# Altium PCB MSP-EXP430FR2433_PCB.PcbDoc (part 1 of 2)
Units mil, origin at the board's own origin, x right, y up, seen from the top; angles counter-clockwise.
Board outline 2300 x 2900 mil, 4 copper layers (Top Layer, VCC Layer, GND Layer, Bottom Layer), stack 30.634 mil thick; 130 components, 92 nets, 410 pads, 310 vias.
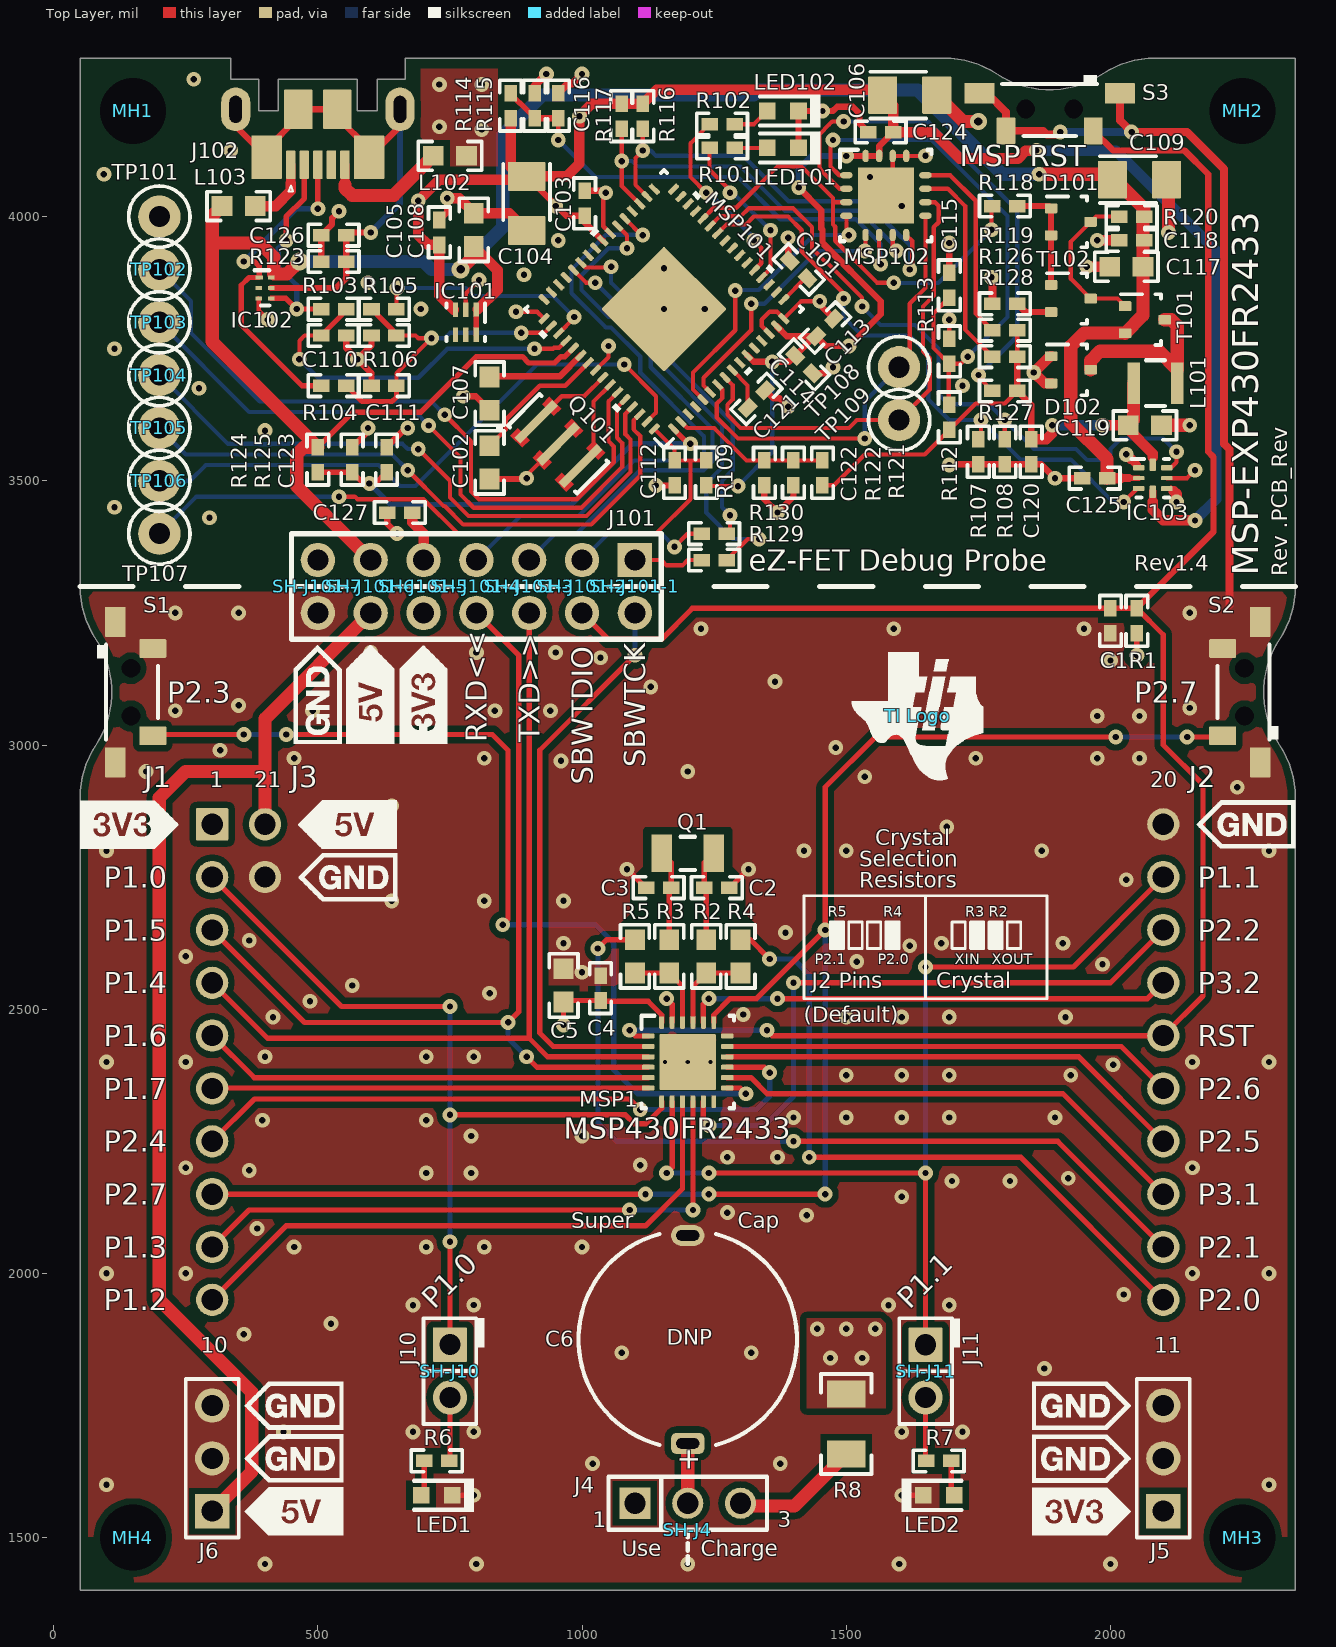
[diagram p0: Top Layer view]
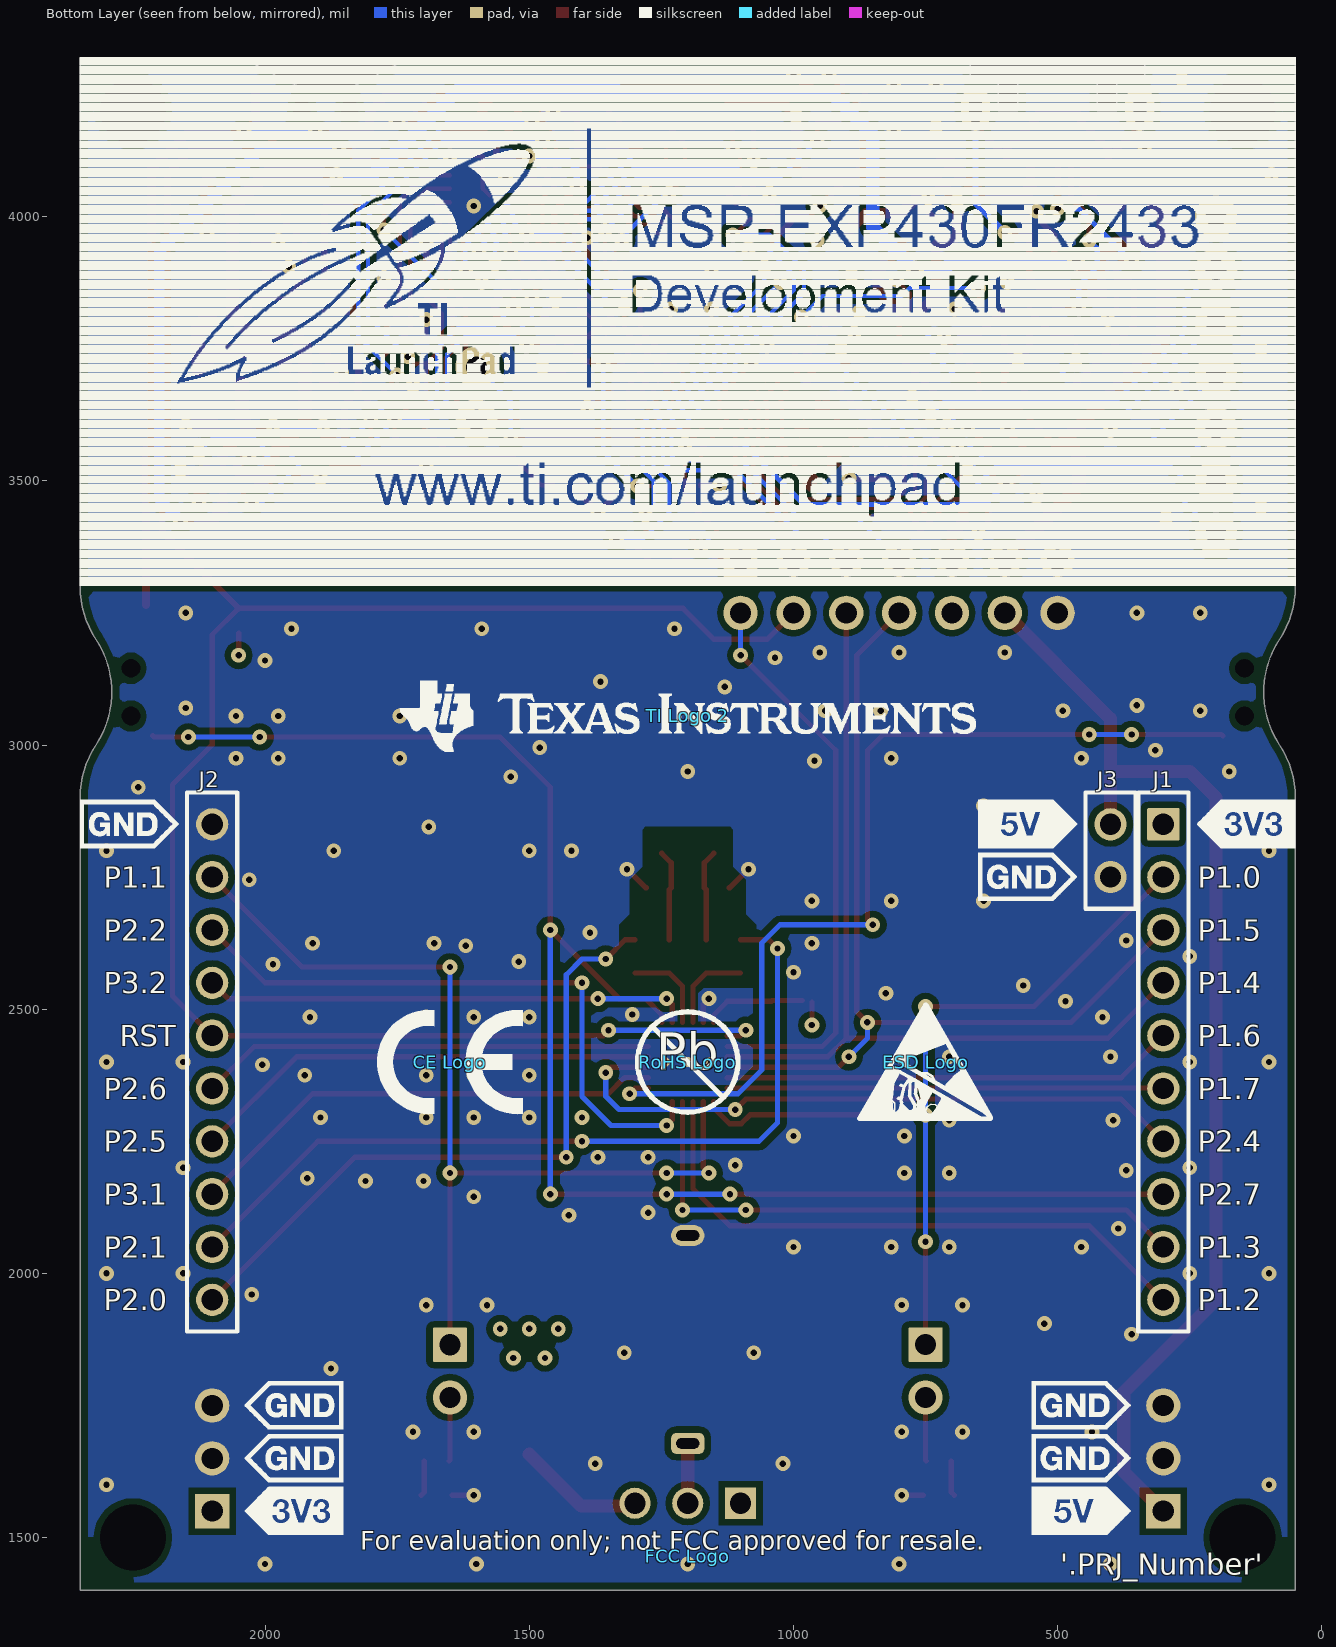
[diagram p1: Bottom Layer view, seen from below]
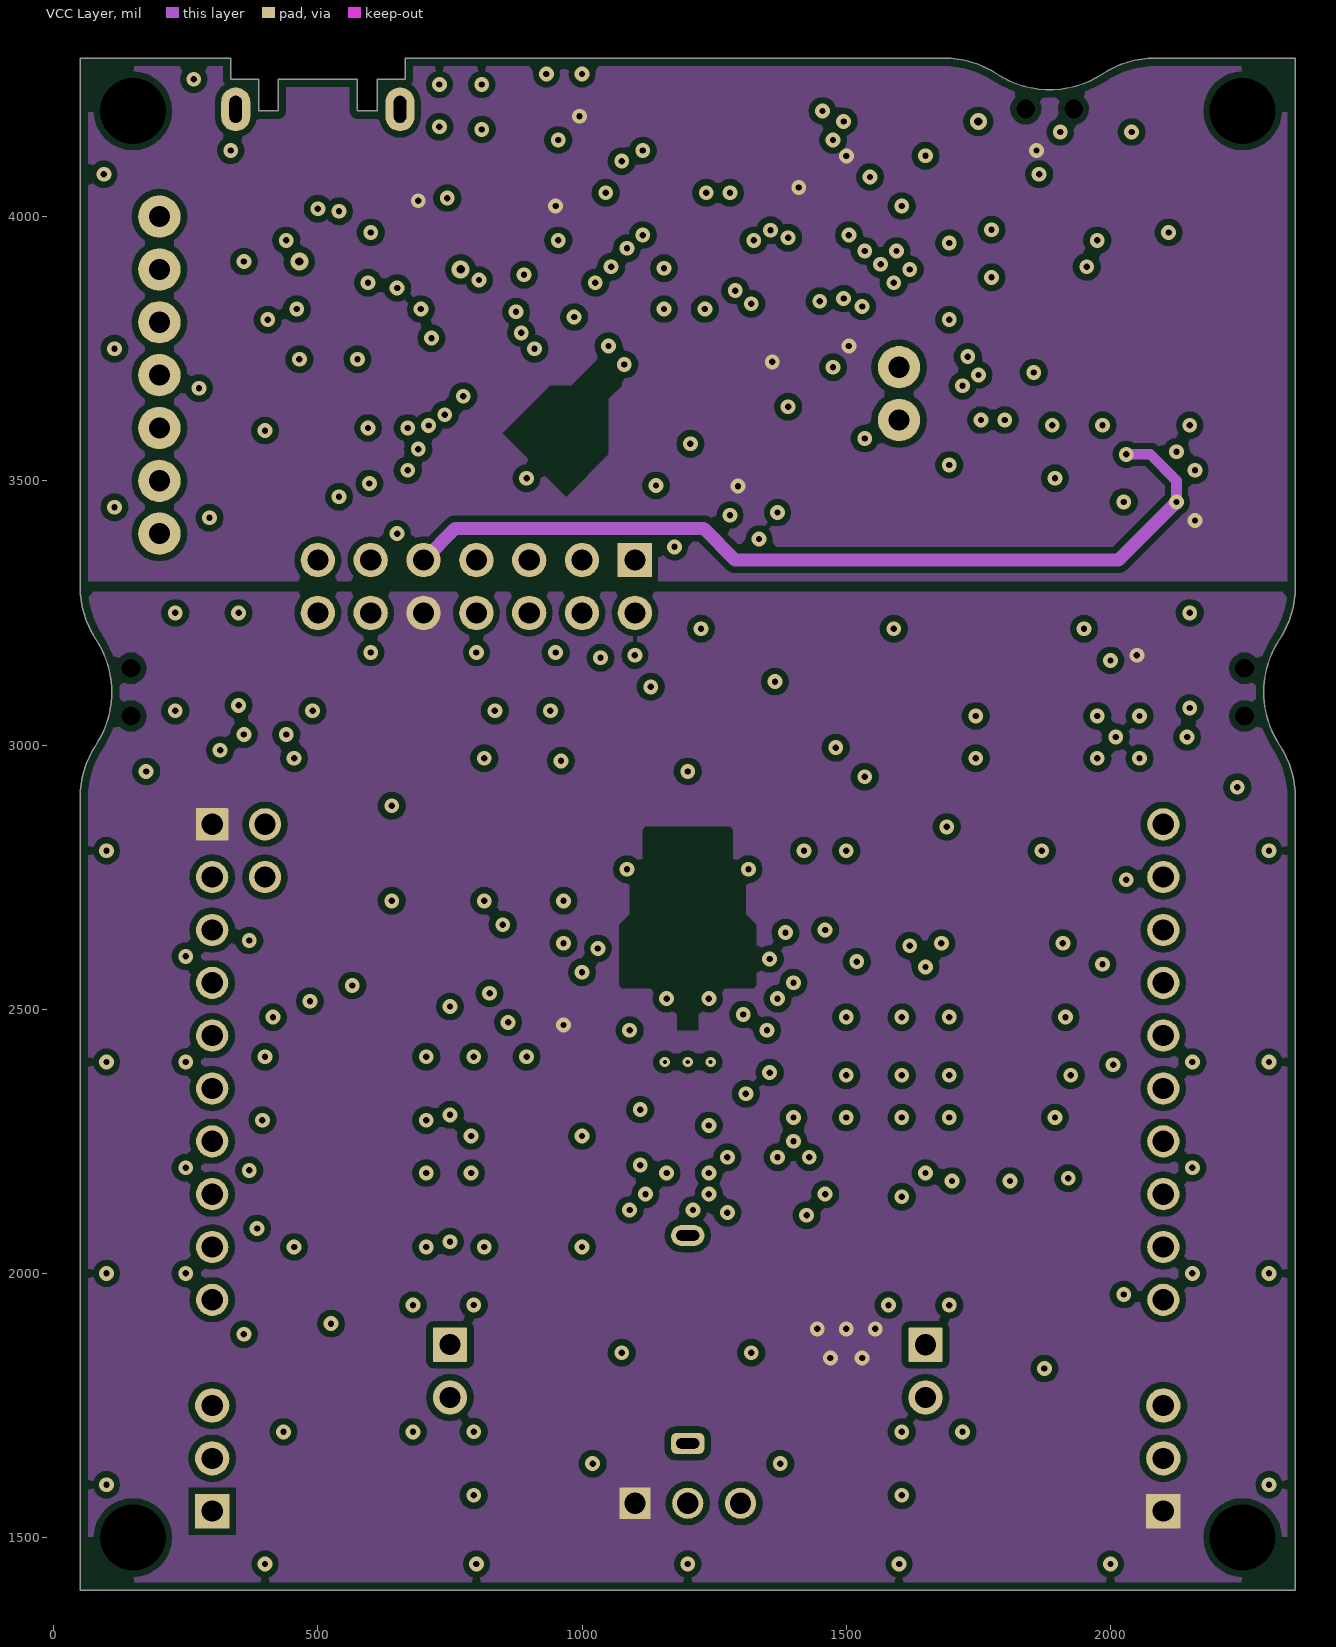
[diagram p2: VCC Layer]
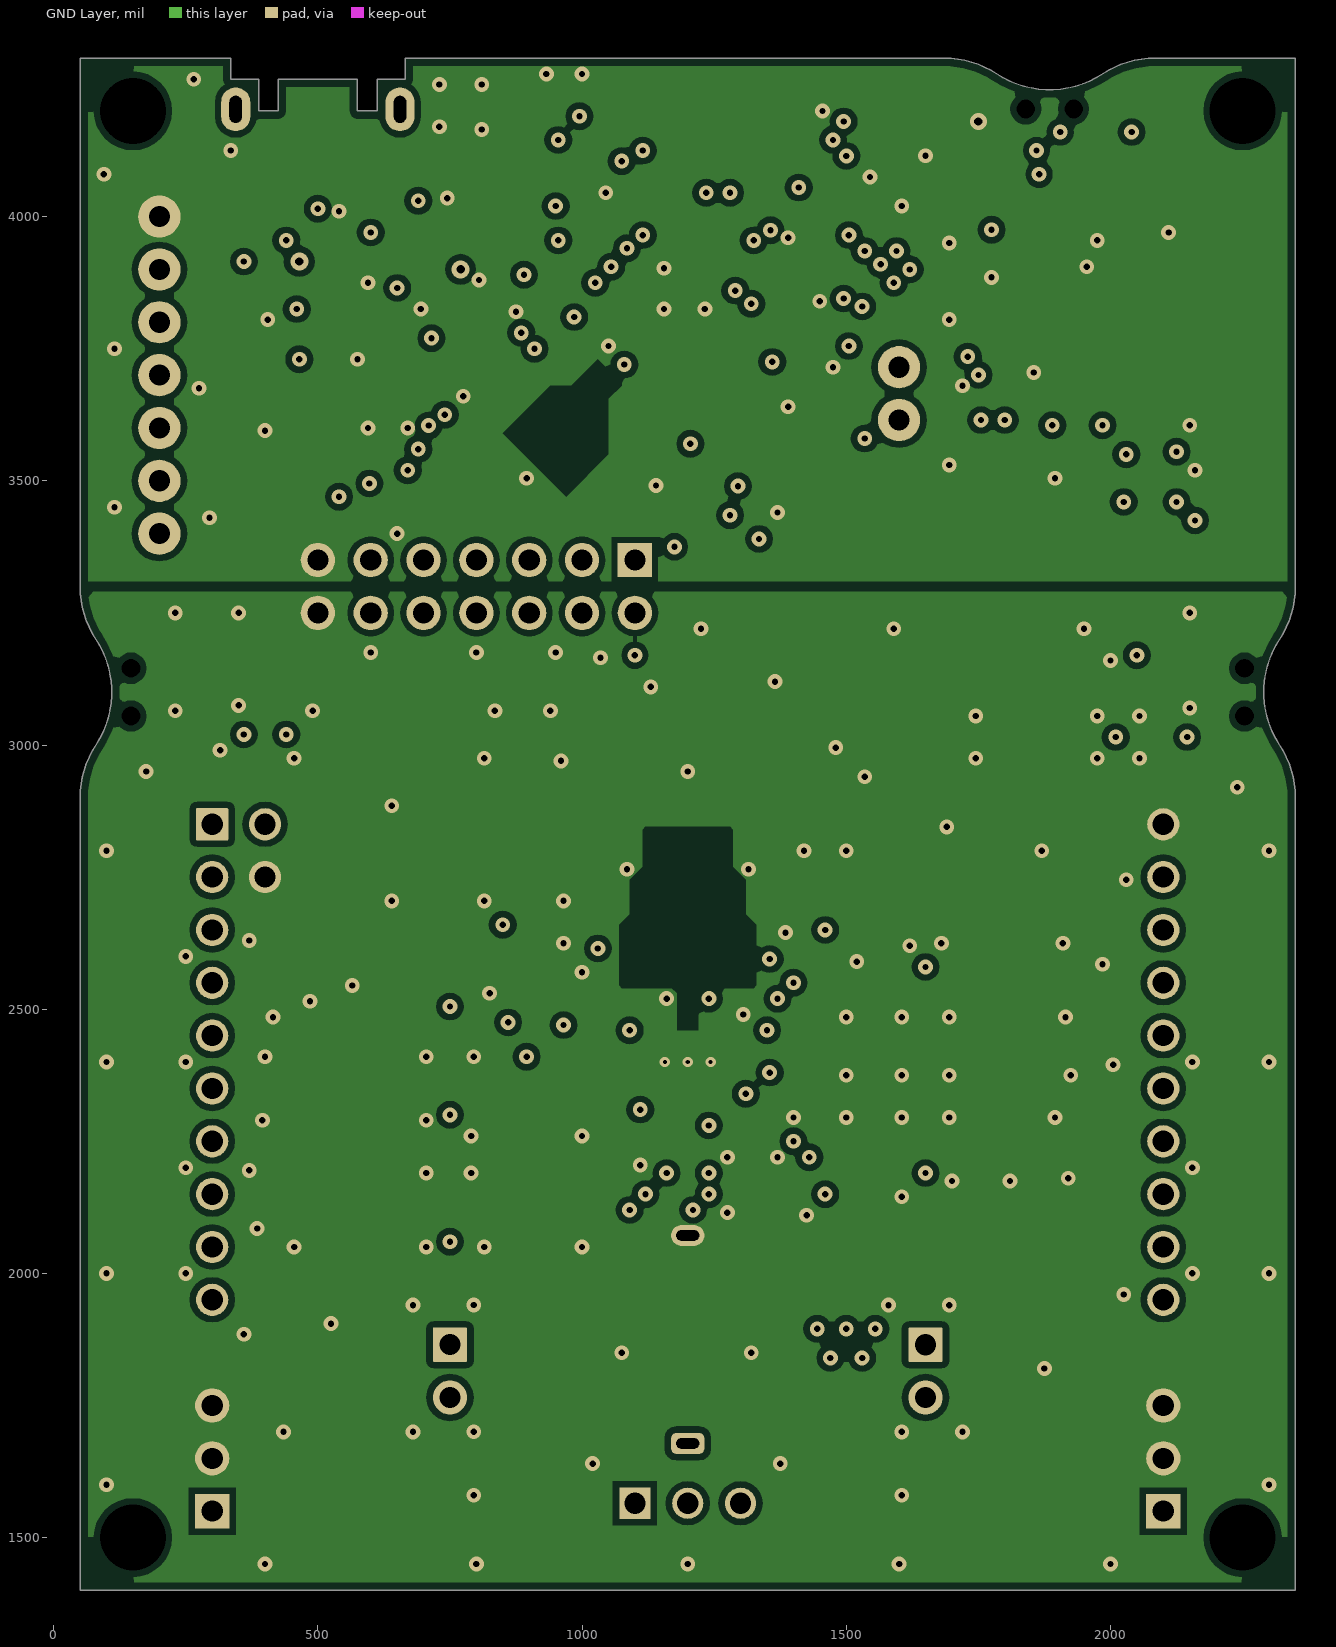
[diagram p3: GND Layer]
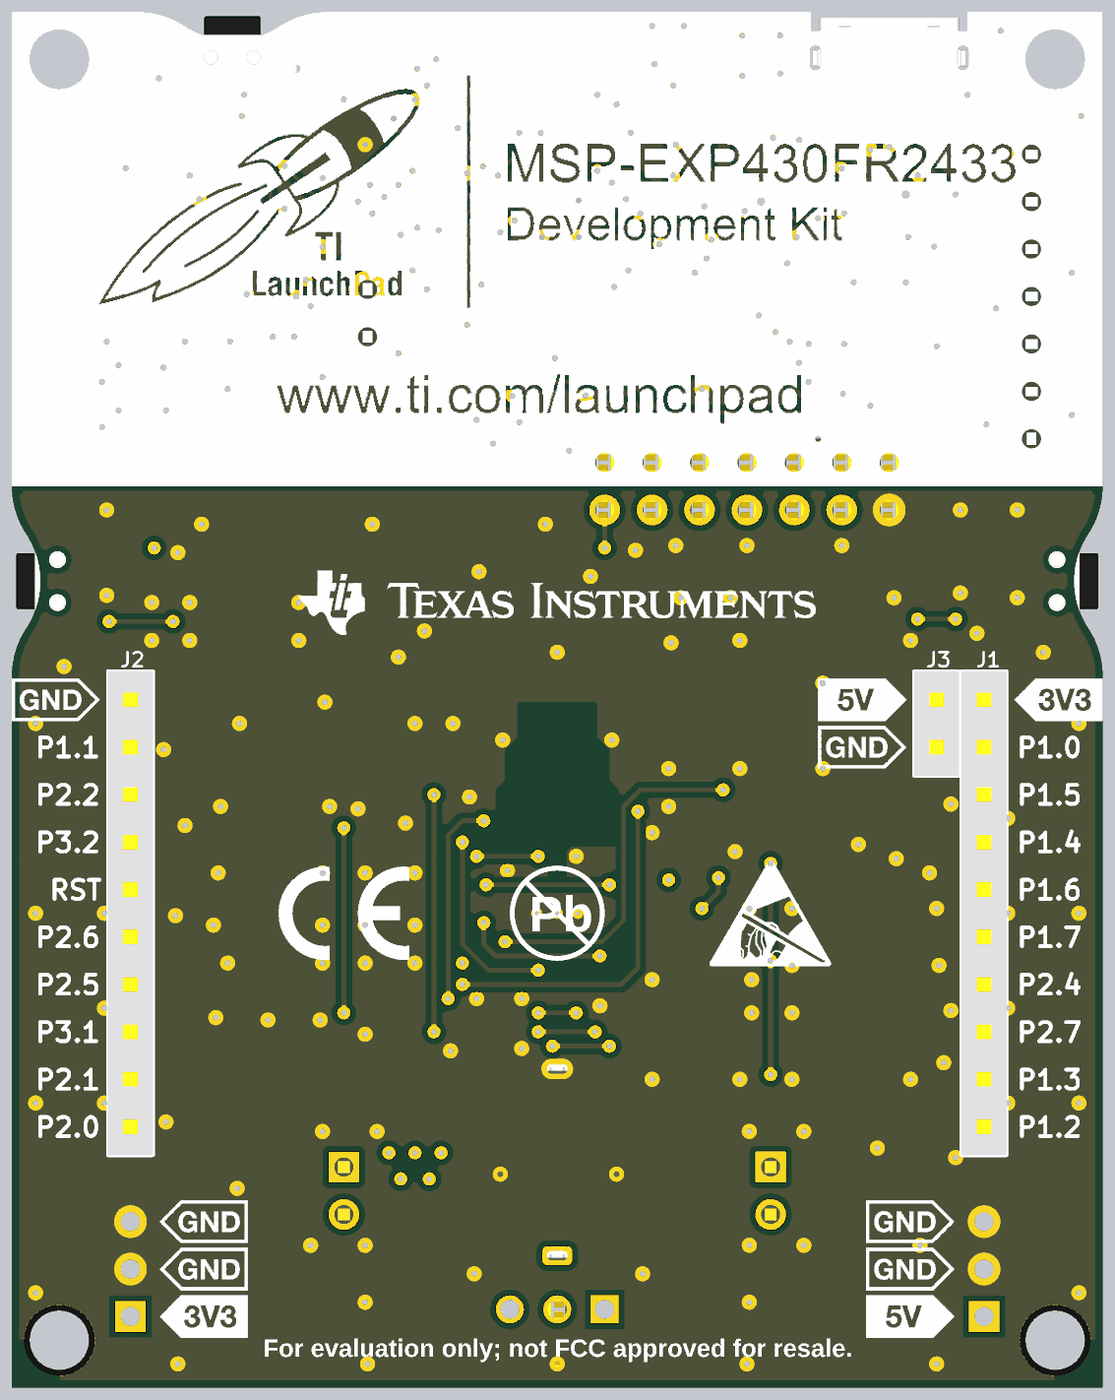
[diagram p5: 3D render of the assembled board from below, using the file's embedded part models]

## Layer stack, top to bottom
Top Solder: solder mask 0.4, Solder Resist, Dk 3.5
Top Layer: signal copper 1.4
Dielectric 2: core 10, Dk 4.2
VCC Layer: signal copper 1.417
Dielectric1: prepreg 5, FR-4, Dk 4.2
GND Layer: signal copper 1.417
Dielectric 3: core 10, Dk 4.2
Bottom Layer: signal copper 1.4
Bottom Solder: solder mask 0.4, Solder Resist, Dk 3.5

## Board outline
50,1400 50,2900 cw(c231.67,2900) 80,3000 ccw(c-71.67,3100) 80,3200 cw(c231.67,3300) 50,3300 50,4300 335,4300 335,4260 388,4260 388,4200 425,4200 425,4260 575,4260 575,4200 612,4200 612,4260 665,4260 665,4300 1685,4300 cw(c1685,4118.33) 1785,4270 ccw(c1885,4421.67) 1985,4270 cw(c2085,4118.33) 2085,4300 2350,4300 2350,3300 cw(c2168.33,3300) 2320,3200 ccw(c2471.67,3100) 2320,3000 cw(c2168.33,2900) 2350,2900 2350,1400

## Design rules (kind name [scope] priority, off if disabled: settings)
AcuteAngle [All] p1: minimum=4.50000000000000E+0001 checktracksonly=FALSE
AssemblyTestPointUsage [All] p1: valid=2
BoardOutlineClearance BoardOutlineClearance_MountingHoles [OnCopper and InComponentClass('Mounting Holes')] p1: gap=15
BoardOutlineClearance BoardOutlineClearance_Poly [OnCopper and IsPoly] p2: gap=15
BoardOutlineClearance [OnCopper and Not InComponentClass('Logo') and not InComponentClass('FiducialMark') and not InRegion(1000,500,4000,800) and not InPoly] p3: gap=10
Clearance Clearance_Keepouts [((IsTrack Or IsArc) And Not InPoly) And IsFree and IsKeepOut vs ((IsTrack Or IsArc) And Not InPoly) And IsFree and IsKeepOut] p1: gap=0
Clearance Clearance_Poly [InPolygon] p2: gap=12
Clearance [All] p3: gap=7.87
ComponentClearance ComponentClearance_MountingHoles_FiducialMarks [InComponentClass('Mounting Holes') vs InComponentClass('FiducialMark')] p1: gap=50 collisioncheckmode=3 verticalgap=10 showdistances=FALSE
ComponentClearance ComponentClearance_Shunt [InComponentClass('Header') vs InComponentClass('Shunt')] p2: gap=0 collisioncheckmode=3 verticalgap=0 showdistances=FALSE
ComponentClearance ComponentClearance_Logo [InComponentClass('Logo')] p3: gap=0 collisioncheckmode=3 verticalgap=10 showdistances=FALSE
ComponentClearance ComponentClearance_ScrewToNut [(HasFootprint('NY PMS 440 0025 PH')) vs (HasFootprint('Keystone_1902C'))] p4: gap=5 collisioncheckmode=3 verticalgap=10 showdistances=FALSE
ComponentClearance ComponentClearance_MountingHoles [InComponentClass('Mounting Holes')] p5: gap=0 collisioncheckmode=3 verticalgap=100000 showdistances=FALSE
ComponentClearance ComponentClearance_SmallPassives [HasFootprint('0201*') or HasFootprint('0402*') or HasFootprint('0508') or HasFootprint('0603*') or HasFootprint('0612') or HasFootprint('0805*') or HasFootprint('0815*') or HasFootprint('0830*') or HasFootprint('1206*') or HasFootprint('1210*') or HasFootprint('1808*') or HasFootprint('1812*') or HasFootprint('1825*') or HasFootprint('2010*') or HasFootprint('2220*') or HasFootprint('2225*') or HasFootprint('2512*') or HasFootprint('2728*') or HasFootprint('3518*') vs HasFootprint('0201*') or HasFootprint('0402*') or HasFootprint('0508') or HasFootprint('0603*') or HasFootprint('0612') or HasFootprint('0805*') or HasFootprint('0815*') or HasFootprint('0830*') or HasFootprint('1206*') or HasFootprint('1210*') or HasFootprint('1808*') or HasFootprint('1812*') or HasFootprint('1825*') or HasFootprint('2010*') or HasFootprint('2220*') or HasFootprint('2225*') or HasFootprint('2512*') or HasFootprint('2728*') or HasFootprint('3518*')] p6: gap=0 collisioncheckmode=3 verticalgap=0 showdistances=FALSE
ComponentClearance ComponentClearance_THtoSMT [IsThruComponent vs IsSMTComponent] p7: gap=0 collisioncheckmode=3 verticalgap=0 showdistances=FALSE
ComponentClearance ComponentClearance_THtoTH [IsThruComponent vs IsThruComponent] p8: gap=0 collisioncheckmode=3 verticalgap=0 showdistances=FALSE
ComponentClearance [All] p9: gap=0 collisioncheckmode=3 verticalgap=0 showdistances=FALSE
DiffPairsRouting [All] p1: maxlimit=100 minlimit=10 mostfreqgap=10 toplayer_minwidth=15 toplayer_maxwidth=15 toplayer_prefwidth=15 midlayer1_minwidth=15 midlayer1_maxwidth=15 midlayer1_prefwidth=15 midlayer2_minwidth=15 midlayer2_maxwidth=15 midlayer2_prefwidth=15 bottomlayer_minwidth=15 bottomlayer_maxwidth=15 bottomlayer_prefwidth=15 maxuncoupledlength=1000
FabricationTestPointUsage TestPointUsage [All] p1: valid=2 allowmultiple=FALSE
FabricationTestpoint Testpoint [All] p1: side=3 testpointundercomponent=TRUE minsize=40 maxsize=100 preferedsize=60 minholesize=0 maxholesize=40 preferedholesize=32 testpointgrid=1 allowsidetop=TRUE allowsidebottom=TRUE usegrid=TRUE gridtolerance=0.01
FanoutControl Fanout_LCC [IsLCC] p1: bgadir=Out bgaviamode=Centered fanoutstyle=Auto fanoutdirection=Alternating viagrid=1 // Fanout_LCC (Default Rule)
FanoutControl Fanout_BGA [IsBGA] p2: bgadir=Out bgaviamode=Centered fanoutstyle=Auto fanoutdirection=Alternating viagrid=1 // Fanout_BGA (Default Rule)
FanoutControl Fanout_Default [All] p4: bgadir=Out bgaviamode=Centered fanoutstyle=Auto fanoutdirection=Alternating viagrid=1 // Fanout_Default (Default Rule)
FanoutControl Fanout_Small [(CompPinCount < 5)] p5: bgadir=Out bgaviamode=Centered fanoutstyle=Auto fanoutdirection=OutThenIn viagrid=1 // Fanout_Small (Default Rule)
HoleSize [All] p1: absolutevalues=TRUE maxlimit=251 minlimit=7.87 maxpercent=80.000 minpercent=20.000
MinimumAnnularRing MinimumAnnularRing_ThermalPadVias [IsVia and InAnyComponent] p1: minimumring=5.91
MinimumAnnularRing [All] p2: minimumring=8
MinimumSolderMaskSliver MinimumSolderMaskSliver_Logo [InComponentClass('Logo') vs InComponentClass('Logo')] p1: minsoldermaskwidth=0.7
MinimumSolderMaskSliver [All] p2: minsoldermaskwidth=3.94
PlaneClearance [All] p1: clearance=10
PlaneConnect [All] p1: planeconnectstyle=Relief reliefexpansion=10 reliefentries=4 reliefconductorwidth=10 reliefairgap=10
PolygonConnect [All] p1: connectstyle=Direct reliefconductorwidth=10 reliefentries=4 polygonreliefangle="90 Angle" airgapwidth=10
RoutingVias ThermalPadVias [IsVia and InAnyComponent] p1: holewidth=7.87 width=19.68 viastyle="Through Hole" minholewidth=7.87 minwidth=19.68 maxholewidth=16 maxwidth=30
RoutingVias [All] p2: holewidth=12 width=28 viastyle="Through Hole" minholewidth=7.87 minwidth=26 maxholewidth=40 maxwidth=65
SilkToBoardRegionClearance [Not ((IsComment or IsDesignator) And (Hide <> 'False')) and not InRegion(1000,500,4000,800)] p1:
SilkToSilkClearance SilkToSilkClearance_Pb-FreeLogo [(HasFootprint('Pb-Free_Overlay_Medium') OR HasFootprint('Pb-Free_Overlay_Small')) vs (HasFootprint('Pb-Free_Overlay_Medium') OR HasFootprint('Pb-Free_Overlay_Small'))] p1: silktosilkclearance=0
SilkToSilkClearance [All] p2: silktosilkclearance=4
SilkToSolderMaskClearance SilkToComponentPadClearance [(IsPad or IsFill or IsRegion) and InAnycomponent] p1: minsilkscreentomaskgap=5 clearancetoexposedcopper=TRUE
SilkToSolderMaskClearance "Silk to Solder Mask Opening" [All] p2: minsilkscreentomaskgap=4 clearancetoexposedcopper=FALSE
SolderMaskExpansion SolderMaskExpansion_via [isvia] p1: expansion=-17
SolderMaskExpansion [All] p2: expansion=1.97
Width [All] p1: maxlimit=100 minlimit=6 preferedwidth=10 checkconnectedcopper=TRUE
14 further rules are at their usual default settings.

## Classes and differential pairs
component class Shunt: SH-J4 SH-J10 SH-J11 SH-J101-1 SH-J101-2 SH-J101-3 SH-J101-4 SH-J101-5 SH-J101-6 SH-J101-7
component class Logo: "TI Logo" "TI Logo 2"
component class LaunchPad_Hardware: "CE Logo" "ESD Logo" "FCC Logo" MH1 MH2 MH3 MH4 "RoHS Logo" "TI Logo" "TI Logo 2"
component class Header: J4 J5 J6 J10 J11 J101
component class LaunchPad_eZFET_1.4: C101 C102 C103 C104 C105 C106 C107 C108 C109 C110 C111 C112 C113 C114 C115 C116 C117 C118 C119 C120 C121 C122 C123 C124 C125 C126 C127 D101 D102 IC101 IC102 IC103 J101 J102 L101 L102 L103 LED101 LED102 MSP101 MSP102 Q101 R101 R102 R103 R104 R105 R106 R107 R108 R109 R112 R113 R114 R115 R116 R117 R118 R119 R120 R121 R122 R123 R124 R125 R126 R127 R128 R129 R130 SH-J101-1 SH-J101-2 SH-J101-3 SH-J101-4 SH-J101-5 SH-J101-6 SH-J101-7 T101 T102 TP101 TP102 TP103 TP104 TP105 TP106 TP107 TP108 TP109
component class LaunchPad_TargetDevice: C1 C2 C3 C4 C5 C6 J1 J2 J3 J4 J5 J6 J10 J11 LED1 LED2 MSP1 Q1 R1 R2 R3 R4 R5 R6 R7 R8 S1 S2 S3 SH-J4 SH-J10 SH-J11

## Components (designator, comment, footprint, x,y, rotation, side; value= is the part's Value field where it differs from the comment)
C1 "GRM155R71H102KA01D" 0402 2000,3235 r270 top
C2 "GRM1555C1E120JA01D" 0402 1255,2730 r0 top
C3 "GRM1555C1E120JA01D" 0402 1145,2730 r180 top
C4 "GRM155R61H104ME14D" 0402 1035,2540 r90 top
C5 "GRM188R60J106ME84" 0603 965,2545 r270 top
C6 "EEC-S0HD224H" SD_1050x600 1200,1875 r90 top
C101 "GRM155R61C474KE01" 0402 1410,3900 r315 top
C102 "GRM188R61C224KA88D" 0603 825,3535 r90 top
C103 "GRM155R61A104KA01D" 0402 1005,4025 r270 top
C104 "293D106X0010A2TE3" 3216-18 895,4025 r270 top
C105 "GRM155R61A104KA01D" 0402 730,3970 r270 top
C106 "293D475X9010A2TE3" 3216-18 1620,4230 r0 top
C107 "GRM188R61C224KA88D" 0603 825,3665 r90 top
C108 "GRM185R61A105KE36D" 0603 795,3975 r270 top
C109 "293D475X9010A2TE3" 3216-18 2055,4070 r0 top
C110 "GRM1555C1H100JA01D" 0402 530,3775 r0 top
C111 "GRM1555C1H100JA01D" 0402 625,3680 r180 top
C112 "GRM155R71H102KA01D" 0402 1175,3515 r90 top
C113 "GRM155R61A104KA01D" 0402 1460,3790 r225 top
C114 "GRM155R61A104KA01D" 0402 1420,3720 r135 top
C115 "GRM1555C1H330JA01D" 0402 1695,3870 r270 top
C116 "GRM1555C1H330JA01D" 0402 955,4210 r270 top
C117 "GRM188R61C475KAAJ" 0603 2030,3905 r0 top
C118 "GRM155R61A104KA01D" 0402 2040,3955 r0 top
C119 "GRM188R61C475KAAJ" 0603 2065,3605 r180 top
C120 "GRM155R61A104KA01D" 0402 1850,3555 r90 top
C121 "GRM155R61A104KA01D" 0402 1330,3655 r225 top
C122 "GRM1555C1H330JA01D" 0402 1345,3515 r90 top
C123 "GRM1555C1H330JA01D" 0402 630,3540 r270 top
C124 "GRM155R61A104KA01D" 0402 1565,4160 r0 top
C125 "GRM155R61A104KA01D" 0402 1970,3505 r0 top
C126 "GRM155R61A224KE19D" 0402 530,3965 r0 top
C127 "GRM1555C1H101JA01D" 0402 655,3440 r180 top
"CE Logo" "CE Mark" CE_Mark_5mm 1650,2400 r180 bottom
D101 "BAS40-05W,115" SOT-323 1925,3990 r0 top
D102 "BAS40-05W,115" SOT-323 1925,3710 r0 top
"ESD Logo" "ESD Susceptible" ESD_Overlay_Medium 750,2400 r180 bottom
"FCC Logo" "FCC disclaimer" FCC_disclaimer 1200,1465 r90 bottom
IC101 "TLV70033DSET" DSE0006A 780,3800 r270 top
IC102 "TPD4E004DRYR" DRY0006A 400,3865 r0 top
IC103 "TS5A21366RSER" RSE0008A 2080,3505 r0 top
J1 "SSQ-110-03-F-S" BoosterPack_20pin_J1 300,2400 r180 bottom
J2 "SSQ-110-03-F-S" BoosterPack_20pin_J2 2100,2400 r180 bottom
J3 "SSQ-102-03-F-S" BoosterPack_20pin_J3 400,2800 r180 bottom
J4 "PEC03SAAN" CONN_PEC03SAAN 1200,1565 r0 top
J5 "PEC03SAAN" PEC03SAAN_Launchpad_3V3 2100,1650 r90 top
J6 "PEC03SAAN" PEC03SAAN_Launchpad_5V0 300,1650 r90 top
J10 "TSW-102-07-G-S" TSW-102-07-G-S 750,1815.14 r270 top
J11 "TSW-102-07-G-S" TSW-102-07-G-S 1650,1815 r270 top
J101 "PEC07DAAN" PEC07DAAN_Launchpad_EZ-FET 800,3300 r180 top
J102 "1051640001" Molex_1051640001 500,4260 r180 top
L101 "CBC2518T2R2M" CBC2518 2085,3685 r180 top
L102 "742792622" 0603 750,4115 r0 top
L103 "742792622" 0603 350,4020 r180 top
LED1 "LTST-C190CKT" LED_LTST-C190_Red 725,1580.14 r0 top
LED2 "LTST-C190GKT" LED_LTST-C190 1675,1580 r180 top
LED101 "LTST-C190CKT" LED_LTST-C190_Red 1380,4130 r0 top
LED102 "LTST-C190GKT" LED_LTST-C190 1380,4200 r0 top
MH1 "MTG_NoPads" NPTH125mil 150,4200 r0 top
MH2 "MTG_NoPads" NPTH125mil 2250,4200 r0 top
MH3 "MTG_NoPads" NPTH125mil 2250,1500 r0 top
MH4 "MTG_NoPads" NPTH125mil 150,1500 r0 top
MSP1 "MSP430FR2433IRGER" RGE0024H 1200,2400 r0 top
MSP101 "MSP430F5528IRGCT" RGC0064B 1155,3825 r135 top
MSP102 "MSP430G2452IRSA16R" RSA0016B 1575,4040 r0 top
Q1 "X1A0001410014" Epson_FC-135 1200,2795 r0 top
Q101 "CSTCR4M00G15L99-R0" Murata_CSTCR 955,3570 r315 top
R1 "RC0402FR-0747KL" 0402 2050,3235 r270 top
R2 "CRCW06030000Z0EA" 0603 1235,2600 r270 top
R3 "CRCW06030000Z0EA" 0603 1165,2600 r270 top
R4 "CRCW06030000Z0EA" 0603 1300,2600 r270 top
R5 "CRCW06030000Z0EA" 0603 1100,2600 r270 top
R6 "RC0402FR-07470RL" 0402 725,1645.14 r0 top
R7 "CRCW0402392RFKED" 0402 1675,1645 r180 top
R8 "CRCW120622R0JNEA" 1206 1500,1715 r270 top
R101 "CRCW0402470RJNED" 0402 1265,4130 r180 top
R102 "CRCW0402390RJNED" 0402 1265,4175 r180 top
R103 "CRCW040227R0JNED" 0402 530,3825 r0 top
R104 "CRCW040227R0JNED" 0402 530,3680 r0 top
R105 "CRCW04021K40FKED" 0402 625,3825 r180 top
R106 "CRCW04021M00JNED" 0402 625,3775 r0 top
R107 "CRG0402F4K7" 0402 1750,3555 r90 top
R108 "CRG0402F4K7" 0402 1800,3555 r90 top
R109 "CRCW040247K0JNED" 0402 1235,3515 r90 top
R112 "CRCW0402221KFKED" 0402 1695,3620 r90 top
R113 "CRCW0402221KFKED" 0402 1695,3745 r90 top
R114 "CRCW0402221KFKED" 0402 865,4210 r90 top
R115 "CRCW0402221KFKED" 0402 910,4210 r90 top
R116 "CRCW04024K70JNED" 0402 1115,4190 r270 top
R117 "CRCW04024K70JNED" 0402 1075,4190 r270 top
R118 "RC0402FR-07820RL" 0402 1800,4020 r180 top
R119 "CRCW04020000Z0ED" 0402 1800,3835 r0 top
R120 "CRCW0402470RJNED" 0402 2040,4000 r0 top
R121 "CRCW0402221KFKED" 0402 1455,3515 r90 top
R122 "CRCW0402221KFKED" 0402 1400,3515 r270 top
R123 "CRCW040233K0JNED" 0402 530,3915 r0 top
R124 "CRCW0402240KFKED" 0402 500,3540 r270 top
R125 "CRCW0402150KFKED" 0402 565,3540 r90 top
R126 "CRCW04022K20FKED" 0402 1800,3785 r0 top
R127 "ERJ-2RKF3301X" 0402 1800,3670 r0 top
R128 "CRCW04026K81FKED" 0402 1800,3735 r180 top
R129 "CRCW040210R0FKED" 0402 1250,3350 r180 top
R130 "CRCW040210R0FKED" 0402 1250,3400 r180 top
"RoHS Logo" "Pb-Free Symbol" Pb-Free_Overlay_Medium 1200,2400 r180 bottom
S1 "1188E-1K2-V-TR" SW_1188E 160,3100 r0 top
S2 "1188E-1K2-V-TR" SW_1188E 2240,3100 r180 top
S3 "1188E-1K2-V-TR" SW_1188E 1885,4190 r270 top
SH-J4 "SNT-100-BK-G" SNT-100-BK-G 1200,1515 r270 top
SH-J10 "SNT-100-BK-G" SNT-100-BK-G 750,1815.14 r90 top
SH-J11 "SNT-100-BK-G" SNT-100-BK-G 1650,1815 r90 top
SH-J101-1 "SNT-100-BK-G" SNT-100-BK-G 1100,3300 r90 top
SH-J101-2 "SNT-100-BK-G" SNT-100-BK-G 1000,3300 r90 top
SH-J101-3 "SNT-100-BK-G" SNT-100-BK-G 900,3300 r90 top
SH-J101-4 "SNT-100-BK-G" SNT-100-BK-G 800,3300 r90 top
SH-J101-5 "SNT-100-BK-G" SNT-100-BK-G 700,3300 r90 top
SH-J101-6 "SNT-100-BK-G" SNT-100-BK-G 600,3300 r90 top
SH-J101-7 "SNT-100-BK-G" SNT-100-BK-G 500,3300 r90 top
T101 "DMG1013UW-7" SOT-323 2065,3805 r0 top
T102 "BC850CW,115" SOT-323 1925,3845 r0 top
"TI Logo" "Texas Instruments" TI_Symbol_Overlay_Medium 1635,3055 r0 top
"TI Logo 2" "Texas Instruments" TI_Horizontal_Overlay_Small 1200,3055 r180 bottom
TP101 "5001" Keystone5001 200,4000 r90 top
TP102 "5001" Keystone5001 200,3900 r90 top
TP103 "5001" Keystone5001 200,3800 r90 top
TP104 "5001" Keystone5001 200,3700 r90 top
TP105 "5001" Keystone5001 200,3600 r90 top
TP106 "5001" Keystone5001 200,3500 r90 top
TP107 "5001" Keystone5001 200,3400 r0 top
TP108 "5001" Keystone5001 1600,3715 r0 top
TP109 "5001" Keystone5001 1600,3615 r0 top

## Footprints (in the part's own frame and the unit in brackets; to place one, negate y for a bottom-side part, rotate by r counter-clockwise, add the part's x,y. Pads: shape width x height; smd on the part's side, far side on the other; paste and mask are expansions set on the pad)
0402 [mm] "0402 from SM-752 data"
  rect 0.8x0.6 smd: 1(-0.6,0) 2(0.6,0)
  silkscreen extent -1.22,-0.52 1.22,0.52, body extent -0.55,-0.3 0.55,0.3, height 0.6
0603 [mm] "0603 from SM-752 data"
  rect 1x0.95 smd: 1(-0.8,0) 2(0.8,0)
  silkscreen extent -1.52,-0.69 1.52,0.69, body extent -0.87,-0.47 0.87,0.47, height 1
1206 [mm] "1206 from SM-752 data"
  rect 1.3x1.85 smd: 1(-1.45,0) 2(1.45,0)
  silkscreen extent -2.4,-1.21 2.4,1.21, body extent -1.7,-0.9 1.7,0.9, height 1.35
3216-18 [mm] "Based on AVX recommendation in http://www.avx.com/download/software/literature/AVX-Footprint-Library.pdf"
  rrect7% 1.4x1.8 smd: 1(-1.3,0) 2(1.3,0)
  silkscreen extent -1.9,-1.12 0.8,1.12, body extent -1.7,-0.9 1.7,0.9, height 1.82
BoosterPack_20pin_J1 [mm] "Receptacle, 2.54mm, 10x1, TH"
  rrect6% 1.55x1.55 hole 1.02: 1(0,11.43)
  round 1.55 hole 1.02: 2(0,8.89) 3(0,6.35) 4(0,3.81) 5(0,1.27) 6(0,-1.27) 7(0,-3.81) 8(0,-6.35) 9(0,-8.89) 10(0,-11.43)
  silkscreen extent -1.21,-12.95 6.35,12.95, body extent -1.21,-12.95 1.21,12.95, height 8.51
BoosterPack_20pin_J2 [mm] "Receptacle, 2.54mm, 10x1, TH"
  round 1.55 hole 1.02: 11(0,-11.43) 12(0,-8.89) 13(0,-6.35) 14(0,-3.81) 15(0,-1.27) 16(0,1.27) 17(0,3.81) 18(0,6.35) 19(0,8.89) 20(0,11.43)
  silkscreen extent -6.35,-12.95 1.21,12.95, body extent -1.21,-12.95 1.21,12.95, height 8.51
BoosterPack_20pin_J3 [mm] "Receptacle, 2.54mm, 2x1, TH"
  round 1.55 hole 1.02: 21(0,1.27) 22(0,-1.27)
  silkscreen extent -6.35,-2.79 1.21,2.79, body extent -1.21,-2.79 1.21,2.79, height 8.51
CBC2518 [mm] "Taiyo Yuden"
  rect 0.6x2 smd: 1(-1.05,0) 2(1.05,0)
  silkscreen extent -0.45,-1.1 0.45,1.1, body extent -1.35,-1 1.35,1, height 2
CE_Mark_5mm [mil] "Minimum text height for CE Mark"
  silkscreen extent -138,-98 138,98
CONN_PEC03SAAN [mm] "SULLINS"
  rect 1.5x1.5 hole 1.016: 1(-2.54,0)
  round 1.5 hole 1.016: 2(0,0) 3(2.54,0)
  silkscreen extent -3.81,-1.27 3.81,1.27, body extent -3.84,-1.3 3.84,1.3, height 8.38
DRY0006A [mm] "PSON, 6-Leads, Body 1x1.45mm, Pitch 0.5mm, TI Recommended"
  rect 0.35x0.2 smd: 1(-0.275,0.5)
  rect 0.3x0.2 smd: 2(-0.3,0) 3(-0.3,-0.5) 4(0.3,-0.5) 5(0.3,0) 6(0.3,0.5)
  silkscreen extent -0.5,-0.85 0.2,0.85, body extent -0.53,-0.75 0.53,0.75, height 0.61
DSE0006A [mm] "TI recommended land pattern"
  rect 0.66x0.25 smd: 1(-0.62,0.5)
  rect 0.7x0.25 smd: 2(-0.6,0) 3(-0.6,-0.5) 4(0.6,-0.5) 5(0.6,0) 6(0.6,0.5)
  Top Layer region: -0.3,0.625 -0.25,0.625 -0.15,0.525 -0.15,0.375 -0.3,0.375
  silkscreen extent -0.9,-0.92 0.9,0.92, body extent -0.77,-0.77 0.77,0.77, height 0.8
Epson_FC-135 [mm] "SMD, 2-Leads, Body 3.2x1.5mm"
  rect 1x1.8 smd: 1(-1.25,0) 2(1.25,0)
  silkscreen extent -0.35,-0.8 0.35,0.8, body extent -1.65,-0.8 1.65,0.8, height 0.9
ESD_Overlay_Medium [mil]
  silkscreen extent -127,-109 125,110
FCC_disclaimer [mil]
Keystone5001 [mil] "For Keystone 500x miniature loop terminals"
  round 80 hole 40: 1(0,0)
  silkscreen extent -58,-58 58,58, body extent -49,-49 49,49, height 182
LED_LTST-C190 [mm] "Lite-On"
  rect 0.8x0.8 smd: 1(-0.75,0) 2(0.75,0)
  silkscreen extent -1.1,-0.8 1.8,0.8, body extent -0.85,-0.45 0.85,0.45, height 0.9
LED_LTST-C190_Red [mm] "Lite-On"
  rect 0.8x0.8 smd: 1(-0.75,0) 2(0.75,0)
  silkscreen extent -1.1,-0.8 1.8,0.8, body extent -0.85,-0.45 0.85,0.45, height 0.9
Molex_1051640001 [mm] "Receptacle, USB 2.0, Micro B, 5 Pos, 0.65mm Pitch, R/A, SMT"
  rrect22% 0.45x1.38 smd: 1(1.3,4.11) 2(0.65,4.11) 3(0,4.11) 4(-0.65,4.11) 5(-1.3,4.11)
  rrect7% 1.475x2.1 smd: 6(-2.462,3.75) 11(2.462,3.75)
  rrect100% 1.4x2.1 hole 0.6 slot 1.3 at 90 deg: 7(-3.95,1.45) 10(3.95,1.45)
  rrect7% 1.375x1.9 smd: 8(-0.937,1.45) 9(0.937,1.45)
  silkscreen extent 1.2,5.1 1.4,5.4, body extent -4.1,-0.7 4.1,4.47, height 2.45
Murata_CSTCR [mm] "Murata"
  rect 0.4x2.6 smd mask+0.051: 1(-1.5,0) 2(0,0) 3(1.5,0)
  Top Layer region: 1.1,-1.35 1.1,-0.85 1.9,-0.85 1.9,-1.35
  Top Layer region: 1.1,-1.35 1.1,-0.85 1.9,-0.85 1.9,-1.35
  Top Layer region: 1.1,0.8 1.9,0.8 1.9,1.3 1.1,1.3
  Top Layer region: -1.9,-1.35 -1.9,-0.85 -1.1,-0.85 -1.1,-1.35
  Top Layer region: -1.9,-1.35 -1.9,-0.85 -1.1,-0.85 -1.1,-1.35
  Top Layer region: -1.9,0.8 -1.1,0.8 -1.1,1.3 -1.9,1.3
  Top Layer region: -0.4,-1.35 -0.4,-0.85 0.4,-0.85 0.4,-1.35
  Top Layer region: -0.4,-1.35 -0.4,-0.85 0.4,-0.85 0.4,-1.35
  Top Layer region: -0.4,0.8 0.4,0.8 0.4,1.3 -0.4,1.3
  silkscreen extent -2.61,-1.56 2.32,1.08, body extent -2.3,-1.05 2.3,1.05, height 1.2
NPTH125mil [mil]
  round 120 hole 125 unplated mask+15: 1(0,0)
Pb-Free_Overlay_Medium [mil]
  silkscreen extent -95,-95 95,95
PEC03SAAN_Launchpad_3V3 [mm] "SULLINS"
  rect 1.65x1.65 hole 1.016: 1(-2.54,0)
  round 1.65 hole 1.016: 2(0,0) 3(2.54,0)
  silkscreen extent -3.81,-1.27 3.81,6.3, body extent -3.84,-1.3 3.84,1.3, height 8.38
PEC03SAAN_Launchpad_5V0 [mm] "SULLINS"
  rect 1.65x1.65 hole 1.016: 1(-2.54,0)
  round 1.65 hole 1.016: 2(0,0) 3(2.54,0)
  silkscreen extent -3.81,-6.31 3.81,1.27, body extent -3.84,-1.3 3.84,1.3, height 8.38
PEC07DAAN_Launchpad_EZ-FET [mm] "Sullins"
  rect 1.65x1.65 hole 1.016: 1(-7.62,-1.27)
  round 1.65 hole 1.016: 2(-7.62,1.27) 3(-5.08,-1.27) 4(-5.08,1.27) 5(-2.54,-1.27) 6(-2.54,1.27) 7(0,-1.27) 8(0,1.27) 9(2.54,-1.27) 10(2.54,1.27) 11(5.08,-1.27) 12(5.08,1.27) 13(7.62,-1.27) 14(7.62,1.27)
  silkscreen extent -8.89,-2.54 8.89,7.57, body extent -8.95,-2.6 8.95,2.6, height 8.38
RGC0064B [mm]
  rrect42% 0.6x0.24 smd mask+0.07: 1(-4.4,3.75) 2(-4.4,3.25) 3(-4.4,2.75) 4(-4.4,2.25) 5(-4.4,1.75) 6(-4.4,1.25) 7(-4.4,0.75) 8(-4.4,0.25) 9(-4.4,-0.25) 10(-4.4,-0.75) 11(-4.4,-1.25) 12(-4.4,-1.75) 13(-4.4,-2.25) 14(-4.4,-2.75) 15(-4.4,-3.25) 16(-4.4,-3.75) 33(4.4,-3.75) 34(4.4,-3.25) 35(4.4,-2.75) 36(4.4,-2.25) 37(4.4,-1.75) 38(4.4,-1.25) 39(4.4,-0.75) 40(4.4,-0.25) 41(4.4,0.25) 42(4.4,0.75) 43(4.4,1.25) 44(4.4,1.75) 45(4.4,2.25) 46(4.4,2.75) 47(4.4,3.25) 48(4.4,3.75)
  rrect42% 0.24x0.6 smd mask+0.07: 17(-3.751,-4.4) 18(-3.251,-4.4) 19(-2.751,-4.4) 20(-2.251,-4.4) 21(-1.75,-4.4) 22(-1.25,-4.4) 23(-0.75,-4.4) 24(-0.25,-4.4) 25(0.25,-4.4) 26(0.75,-4.4) 27(1.25,-4.4) 28(1.75,-4.4) 29(2.251,-4.4) 30(2.751,-4.4) 31(3.251,-4.4) 32(3.751,-4.4) 49(3.751,4.4) 50(3.251,4.4) 51(2.751,4.4) 52(2.251,4.4) 53(1.75,4.4) 54(1.25,4.4) 55(0.75,4.4) 56(0.25,4.4) 57(-0.25,4.4) 58(-0.75,4.4) 59(-1.25,4.4) 60(-1.75,4.4) 61(-2.251,4.4) 62(-2.751,4.4) 63(-3.251,4.4) 64(-3.751,4.4)
  rrect8% 1.19x1.19 on Top Paste: 65(-1.39,-1.39) 65(-1.39,1.39) 65(-1.39,0) 65(0,1.39) 65(0,0) 65(0,-1.39) 65(1.39,0) 65(1.39,-1.39) 65(1.39,1.39)
  rrect2% 4.25x4.25 smd paste-2.112: 65(0,0)
  silkscreen extent -5.1,-5.1 5.1,5.1, body extent -4.57,-4.57 4.57,4.57, height 1.01
RGE0024H [mm] "QFN, 24-Leads, Body 4x4mm, Pitch 0.5mm, Thermal Pad 2.7x2.7mm, TI Recommended"
  rrect42% 0.6x0.24 smd: 1(-1.9,1.25) 2(-1.9,0.75) 3(-1.9,0.25) 4(-1.9,-0.25) 5(-1.9,-0.75) 6(-1.9,-1.25) 13(1.9,-1.25) 14(1.9,-0.75) 15(1.9,-0.25) 16(1.9,0.25) 17(1.9,0.75) 18(1.9,1.25)
  rrect42% 0.24x0.6 smd: 7(-1.25,-1.9) 8(-0.75,-1.9) 9(-0.25,-1.9) 10(0.25,-1.9) 11(0.75,-1.9) 12(1.25,-1.9) 19(1.25,1.9) 20(0.75,1.9) 21(0.25,1.9) 22(-0.25,1.9) 23(-0.75,1.9) 24(-1.25,1.9)
  rrect8% 1.19x1.19 on Top Paste: 25(-0.695,-0.695) 25(-0.695,0.695) 25(0.695,-0.695) 25(0.695,0.695)
  rrect4% 2.7x2.7 smd paste-1.35: 25(0,0)
  silkscreen extent -2.22,-2.22 2.22,2.22, body extent -2.07,-2.07 2.07,2.07, height 1.01
RSA0016B [mm] "QFN, 16-Leads, Body 4x4mm, Pitch 0.65mm, Thermal Pad 2.7x2.7mm, TI Recommended"
  oval 0.6x0.3 smd: 1(-1.9,0.975) 2(-1.9,0.325) 3(-1.9,-0.325) 4(-1.9,-0.975) 9(1.9,-0.975) 10(1.9,-0.325) 11(1.9,0.325) 12(1.9,0.975)
  oval 0.3x0.6 smd: 5(-0.975,-1.9) 6(-0.325,-1.9) 7(0.325,-1.9) 8(0.975,-1.9) 13(0.975,1.9) 14(0.325,1.9) 15(-0.325,1.9) 16(-0.975,1.9)
  rect 2.7x2.7 smd paste-1.35: 17(0,0)
  silkscreen extent -2.2,-2.2 2.2,2.2, body extent -2.05,-2.05 2.05,2.05, height 1.01
RSE0008A [mm] "QFN, 8-Leads, Body 1.5x1.5mm, Pitch 0.5mm, TI Recommended"
  rrect40% 0.55x0.25 smd: 1(-0.675,0.5) 3(-0.675,-0.5) 5(0.675,-0.5) 7(0.675,0.5)
  rrect50% 0.55x0.2 smd: 2(-0.675,0) 6(0.675,0)
  rrect33% 0.3x0.6 smd: 4(0,-0.65) 8(0,0.65)
  silkscreen extent -1.02,-0.92 0.77,0.92, body extent -0.75,-0.75 0.75,0.75, height 0.6
SD_1050x600 [mm] "TH, 2-Leads, Dia 10.5mm, Pin Spacing 10mm"
  rrect50% 1x1.6 hole 0.5 slot 1.1 at 90 deg: 1(-5,0)
  oval 1x1.6 hole 0.5 slot 1.1 at 90 deg: 2(5,0)
  silkscreen extent -5.07,-5.25 5.07,5.25, body extent -5.25,-5.25 5.6,5.25, height 6
SNT-100-BK-G [mil] "Samtec STEP model"
  round 1 on Mech3: 0(0,0)
  body extent -100,-50 100,50, height 344
SOT-323 [mm] "Diodes Inc recommended land pattern.  2016-02-24"
  rrect21% 0.6x0.47 smd: 1(-0.95,0.65) 2(-0.95,-0.65) 3(0.95,0)
  silkscreen extent -1.14,-1.22 0.77,1.22, body extent -1.13,-1.13 1.12,1.12, height 1.13
SW_1188E [mm] "SMD, 4-Leads, Body 7.8x3.5mm"
  rrect10% 1x1.45 smd: 1(-1.1,3.375) 2(-1.1,-3.375)
  rrect11% 1.3x0.9 smd: 3(0.7,2.1) 4(0.7,-2.1)
  round 0 hole 0.9 unplated: ""(-0.35,-1.15) ""(-0.35,1.15)
  silkscreen extent -1.97,-2.28 0.95,2.28, body extent -2.55,-3.9 1.05,3.9, height 3.5
TI_Horizontal_Overlay_Small [mil]
  silkscreen extent -545,-68 545,67
TI_Symbol_Overlay_Medium [mil]
  silkscreen extent -124,-122 124,120
TSW-102-07-G-S [mm] "Samtec 100mil, 1x2, 230 mil above insulator"
  rrect6% 1.65x1.65 hole 1.016: 1(-1.27,0)
  round 1.65 hole 1.016: 2(1.27,0)
  silkscreen extent -2.54,-1.27 2.54,1.65, body extent -2.54,-1.27 2.54,1.27, height 8.38

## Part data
C1 C112: "CAP, CERM, 1000 pF, 50 V, +/- 10%, X7R, 0402"
C2 C3: "CAP, CERM, 12 pF, 25 V, +/- 5%, C0G/NP0, 0402"
C4: "CAP, CERM, 0.1 µF, 50 V, +/- 20%, X5R, 0402"
C5: "CAP, CERM, 10 µF, 6.3 V, +/- 20%, X5R, 0603"
C6: "CAP, Electric Double Layer, 220000 µF, 5.5 V, +80/-20%, TH"
C101: "CAP, CERM, 0.47 µF, 16 V, +/- 10%, X5R, 0402"
C102 C107: "CAP, CERM, 0.22 µF, 16 V, +/- 10%, X5R, 0603"
C103 C105 C113 C114 C118 C120 C121 C124 C125: "CAP, CERM, 0.1 µF, 10 V, +/- 10%, X5R, 0402"
C104: "CAP, TA, 10 µF, 10 V, +/- 20%, 3.4 ohm, SMD"
C106 C109: "CAP, TA, 4.7 µF, 10 V, +/- 10%, 5 ohm, SMD"
C108: "CAP, CERM, 1 µF, 10 V, +/- 10%, X5R, 0603"
C110 C111: "CAP, CERM, 10 pF, 50 V, +/- 5%, C0G/NP0, 0402"
C115 C116 C122 C123: "CAP, CERM, 33 pF, 50 V, +/- 5%, C0G/NP0, 0402"
C117 C119: "CAP, CERM, 4.7 µF, 16 V, +/- 10%, X5R, 0603"
C126: "CAP, CERM, 0.22 µF, 10 V, +/- 10%, X5R, 0402"
C127: "CAP, CERM, 100 pF, 50 V, +/- 5%, C0G/NP0, 0402"
D101 D102: "Diode, Schottky, 40 V, 0.12 A, AEC-Q101, SOT-323"
"ESD Logo": library part ESD_Susceptible, "ESD Susceptible Symbol"
"FCC Logo": library part FCC_disclaimer, "FCC_disclaimer"
IC101: "Single Output LDO, 200 mA, Fixed 3.3 V Output, 2 to 5.5 V Input, with Low IQ, 6-pin WSON (DSE), -40 to 125 degC, Green (RoHS & no Sb/Br)"
IC102: "ESD-Protection Array for High-Speed Data Interfaces, 4 Channels, -40 to +85 degC, 6-pin SON (DRY), Green (RoHS & no Sb/Br)"
IC103: "0.75-Ohm DUAL SPST ANALOG SWITCH WITH 1.8-V COMPATIBLE INPUT LOGIC, RSE0008A (UQFN-8)"
J1: library part BoosterPack_20pin_J1, "Receptacle, 2.54mm, 10x1, Gold, TH"
J2: library part BoosterPack_20pin_J2, "Receptacle, 2.54mm, 10x1, Gold, TH"
J3: library part BoosterPack_20pin_J3, "Receptacle, 2.54mm, 2x1, Gold, TH"
J4 J5 J6: "Header, 100mil, 3x1, Tin, TH"
J10 J11: "Header, 100mil, 2x1, Gold, TH"
J101: "Header, 100mil, 7x2, Tin, TH"
J102: "Receptacle, USB 2.0, Micro B, 5 Position, R/A, SMT"
L101: "Inductor, Wirewound, Ceramic, 2.2 µH, 0.89 A, 0.13 ohm, SMD"
L102 L103: "Ferrite Bead, 180 ohm @ 100 MHz, 0.5 A, 0603"
LED1 LED101: "LED, Red, SMD"
LED2 LED102: "LED, Green, SMD"
MH1 MH2 MH3 MH4: library part "Mounting Hole (non-standard) No Pad", "PCB Mounting Hole, No Pad"
MSP1: "MSP430FR2433 16 MHz Ultra-Low-Power Microcontroller with 16 KB FRAM, 4 KB RAM, 19 IO, 4 Timers, RGE0024H (VQFN-24)"
MSP101: "25 MHz Mixed Signal Microcontroller with 128 KB Flash, 8192 B SRAM and 47 GPIOs, -40 to 85 degC, 64-pin QFN (RGC), Green (RoHS & no Sb/Br)"
MSP102: "16 MHz Mixed Signal Microcontroller with 8 KB Flash, 256 B SRAM and 16 GPIOs, 16-pin QFN (RSA), Green (RoHS & no Sb/Br)"
Q1: "Crystal, 32.768 KHz, 12.5 pF, SMD"
Q101: "Resonator, 4MHz, 39pF SMD"
R1: "RES, 47.0 k, 1%, 0.0625 W, 0402"
R2 R3 R4 R5: "RES, 0, 5%, 0.1 W, 0603"
R6: "RES, 470, 1%, 0.063 W, 0402"
R7: "RES, 392, 1%, 0.063 W, 0402"
R8: "RES, 22, 5%, 0.25 W, 1206"
R101 R120: "RES, 470, 5%, 0.063 W, 0402"
R102: "RES, 390, 5%, 0.063 W, 0402"
R103 R104: "RES, 27, 5%, 0.063 W, 0402"
R105: "RES, 1.40 k, 1%, 0.063 W, 0402"
R106: "RES, 1.0 M, 5%, 0.063 W, 0402"
R107 R108: "RES, 4.70 k, 1%, 0.063 W, 0402"
R109: "RES, 47 k, 5%, 0.063 W, 0402"
R112 R113 R114 R115 R121 R122: "RES, 221 k, 1%, 0.063 W, 0402"
R116 R117: "RES, 4.7 k, 5%, 0.063 W, 0402"
R118: "RES, 820, 1%, 0.063 W, 0402"
R119: "RES, 0, 5%, 0.063 W, 0402"
R123: "RES, 33 k, 5%, 0.063 W, 0402"
R124: "RES, 240 k, 1%, 0.063 W, 0402"
R125: "RES, 150 k, 1%, 0.063 W, 0402"
R126: "RES, 2.20 k, 1%, 0.063 W, 0402"
R127: "RES, 3.30 k, 1%, 0.1 W, AEC-Q200 Grade 0, 0402"
R128: "RES, 6.81 k, 1%, 0.063 W, 0402"
R129 R130: "RES, 10.0, 1%, 0.063 W, 0402"
"RoHS Logo": library part Pb-Free
S1 S2 S3: "Switch, SPST, 0.05 A, 12 VDC, SMD"
SH-J4 SH-J10 SH-J11 SH-J101-1 SH-J101-2 SH-J101-3 SH-J101-4 SH-J101-5 SH-J101-6 SH-J101-7: "Shunt, 100mil, Gold plated, Black"
T101: "MOSFET, P-CH, -20 V, -0.82 A, SOT-323"
T102: library part "BC850CW,115, NXP Semiconductor", "Transistor, NPN, 45 V, 0.1 A, SOT-323"
"TI Logo" "TI Logo 2": library part TI_Logo, "Texas Instrument Corporate Signature"
TP101 TP102 TP103 TP104 TP105 TP106 TP107 TP108 TP109: "Test Point, Miniature, Black, TH"

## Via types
v1: diameter 28, hole 12, Top Layer to Bottom Layer, 304 vias
v2: diameter 19.68, hole 7.87, Top Layer to Bottom Layer, 3 vias
v3: diameter 34, hole 16, Top Layer to Bottom Layer, 2 vias
v4: diameter 32, hole 16, Top Layer to Bottom Layer, 1 vias

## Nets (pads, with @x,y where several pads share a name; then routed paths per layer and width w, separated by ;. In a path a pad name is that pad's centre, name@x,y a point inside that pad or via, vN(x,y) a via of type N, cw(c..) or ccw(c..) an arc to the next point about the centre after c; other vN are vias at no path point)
3V3: C4.1 C5.2 J1.1 J4.1 J5.1 J101.10 MSP1.24 R1.2 R8.1 | length 278.5
  Top Layer w10: v1(965,2470) C5.2@965,2513.5 ; C5.2@982.87,2516.38 1040,2516.38 1041.38,2515 1125,2515 1150.79,2489.21 MSP1.24@1150.79,2474.8 ; v1(2050,3170) R1.2@2050,3211.38
  other v1: 1470,1840 1530,1840 1445,1895 1500,1895 1555,1895
5V0: J3.21 J6.1 J101.12 | length 2157.1
  Top Layer w25: J6.1@300,1550 375,1625 375,1775 200,1950 200,2900 250,2950 400,2950 ; J3.21@400,2850 400,2950 ; J101.12@600,3250 400,3050 400,2950
A0: J1.2 J10.1 MSP1.7 | length 1623.8
  Top Layer w10: J1.2@300,2750 545,2505 v1(750,2505) ; J10.1@750,1865.14 v1(750,2060) ; v1(750,2300) 1081.99,2300 1098.87,2283.13 1121.13,2283.13 1150.79,2312.78 MSP1.7@1150.79,2325.2
  Bottom Layer w10: v1(750,2060) v1(750,2300) v1(750,2505)
"A1 CLK": J1.7 MSP1.15 | length 1236.2
  Top Layer w10: J1.7@300,2250 380,2330 1090,2330 v1(1110,2310) ; MSP1.15@1274.8,2390.16 1344.84,2390.16 v1(1355,2380)
  Bottom Layer w10: v1(1110,2310) 1330,2310 1355,2335 v1(1355,2380)
"A1 CS": J2.13 MSP1.14 | length 916.5
  Top Layer w10: MSP1.14@1274.8,2370.47 1319.53,2370.47 1350,2340 1910,2340 J2.13@2100,2150
"A1 MISO": J2.14 MSP1.16 | length 891.4
  Top Layer w10: MSP1.16@1274.8,2409.84 1940.16,2409.84 J2.14@2100,2250
"A1 MOSI": J2.15 MSP1.17 | length 858.1
  Top Layer w10: MSP1.17@1274.8,2429.53 2020.47,2429.53 J2.15@2100,2350
A6: J1.5 MSP1.5 | length 858.1
  Top Layer w10: J1.5@300,2450 379.53,2370.47 MSP1.5@1125.2,2370.47
A7: J1.6 MSP1.6 | length 824.4
  Top Layer w10: J1.6@300.79,2350.79 MSP1.6@1125.2,2350.79
B0_SCL: J1.9 MSP1.10 | length 1144.3
  Top Layer w10: J1.9@300,2050 370,2120 v1(1090,2120) ; MSP1.10@1209.84,2325.2 1210,2325.04 v1(1210,2120)
  Bottom Layer w10: v1(1090,2120) v1(1210,2120)
B0_SDA: J1.10 MSP1.9 | length 1142.2
  Top Layer w10: J1.10@300,1950 440,2090 1120,2090 1190.16,2160.16 MSP1.9@1190.16,2325.2
BCL_RXD: J1.3 J101.8 MSP1.4 | length 1766.8
  Top Layer w10: J1.3@300,2650 475,2475 v1(860,2475) 880,2495 880,3170 J101.8@800,3250 ; v1(895,2410) 914.84,2390.16 MSP1.4@1125.2,2390.16
  Bottom Layer w10: v1(860,2475) 860,2445 v1(895,2410)
BCL_TXD: J1.4 J101.6 MSP1.3 | length 1688.3
  Top Layer w10: J1.4@300,2550 405,2445 900,2445 ; J101.6@900,3250 900,2445 ; MSP1.3@1125.2,2409.84 935.16,2409.84 900,2445
EZ_GND: C101.1 C102.1 C103.1 C104.2 C105.1 C106.2 C107.1 C108.1 C109.2 C110.2 C111.2 C112.1 C113.1 C114.1 C115.1 C116.1 C117.1 C118.1 C119.1 C120.1 C121.1 C122.1 C123.1 C124.1 C125.1 C126.1 C127.2 D102.1 D102.2 IC101.2 IC102.3 IC103.6 J101.13 L102.2 LED101.2 LED102.2 MSP101.14 MSP101.16 MSP101.39 MSP101.49 MSP101.56 MSP101.65@1155,3825 MSP102.13 MSP102.14 MSP102.17 Q101.2 R106.1 R107.1 R108.1 R113.2 R115.2 R119.1 R122.2 R123.1 R125.2 TP101.1 | length 3090.9
  Top Layer w8: IC102.3@388.19,3845.31 388.19,3821.81 v1(405,3805) ; IC101.2@780,3823.62 780,3855 v1(805,3880) ; v1(875,3820) 915.02,3820 MSP101.49@928.09,3806.93 ; v1@895,3510 Q101.2@955,3570 ; MSP101.56@1025.55,3709.47 1050,3733.92 v1(1050,3755) ; v1@1040,4040 1040,3981.76 MSP101.39@1053.39,3968.37 ; MSP101.14@1354.05,3779.07 1340,3793.11 1340,3805 1355,3820 1368.79,3820 MSP101.16@1381.89,3806.9 1414.98,3840 v1(1450,3840) ; MSP102.17@1575,4040 1587.8,4052.8 MSP102.14@1587.8,4114.8 MSP102.13@1613.39,4114.8 v1@1649.8,4114.8 ; R113.2@1695,3768.62 v1(1695,3805) ; IC103.6@2106.57,3505 2145,3505 v1(2160,3520)
  Top Layer w12: R123.1@506.38,3915 C126.1@506.38,3965 526.89,3985.51 526.89,3996.89 v1(540,4010) ; C110.2@553.62,3775 553.62,3751.38 v1(575,3730) ; R125.2@565,3563.62 v1@595,3593.62 ; C111.2@601.38,3680 601.38,3703.62 v1(575,3730) ; R106.1@601.38,3775 601.38,3756.38 v1(575,3730) ; C123.1@630,3563.62 v1@666.38,3600 ; C127.2@631.38,3440 631.38,3418.62 v1(650,3400) ; C105.1@730,3993.62 745,4008.62 v1(745,4035) ; v1(775,3660) 798.5,3660 C107.1@825,3633.5 ; C102.1@825,3503.5 893.5,3503.5 v1(895,3505) ; C103.1@1005,4048.62 v1@1041.38,4048.62 ; v1(1140,3491.22) 1174.85,3491.22 C112.1@1175,3491.38 ; C122.1@1345,3491.38 1345,3465 v1(1370,3440) 1400,3470 R122.2@1400,3491.38 ; C121.1@1346.7,3671.7 1362.16,3656.24 1373.76,3656.24 v1(1390,3640) ; v1(1390,3960) 1390,3920 C101.1@1393.3,3916.7 ; LED101.2@1409.53,4130 LED102.2@1409.53,4200 v1(1455,4200) 1475,4200 1482.87,4207.87 1512.13,4207.87 1525,4195 1525,4176.38 C124.1@1541.38,4160 ; C114.1@1436.7,3703.3 1463.3,3703.3 v1(1475,3715) ; v1(1450,3840) 1450,3833.41 C113.1@1476.7,3806.7 ; C115.1@1695,3893.62 v1(1695,3950) ; v1@1696.38,3531.38 R107.1@1750,3531.38 R108.1@1800,3531.38 C120.1@1850,3531.38 1868.62,3531.38 v1(1895,3505) C125.1@1946.38,3505
  Top Layer w15: R115.2@910,4233.62 910,4247.5 v1(932.5,4270) ; C116.1@955,4233.62 972.83,4251.46 981.46,4251.46 v1(1000,4270) ; R119.1@1776.38,3835 v1@1776.38,3883.62
  Top Layer w20: v1(745,4035) 767.17,4035 C108.1@795.67,4006.5 ; C108.1@795,4006.5 C108.1@795.67,4006.5 ; C104.2@895,3973.82 862.32,4006.5 C108.1@795.67,4006.5 ; D102.2@1887.6,3684.41 1875.59,3684.41 v1(1855,3705) 1885.59,3735.59 D102.1@1887.6,3735.59 ; v1(1955,3905) C117.1@1998.5,3905 ; v1(1975,3955) C118.1@2016.38,3955
  Top Layer w25: C106.2@1671.18,4230 1721.18,4180 v4(1750,4180) ; C119.1@2096.5,3605 v1(2150,3605) ; C109.2@2106.18,4070 2110,4066.18 v1(2110,3970)
  other v1: 295,3430 115,3450 1695,3530 400,3595 595,3600 670,3600 275,3675 1720,3680 115,3750 695,3825 1155,3825 1232.39,3825 595,3875 1775,3885 1155,3902.39 1605,4020 1045,4045 1545,4075 95,4080 1650,4115 335,4125 810,4165 730,4170 730,4250 810,4250 265,4260
EZFET_AVBUS: C123.2 MSP101.1 R124.2 R125.1 | length 863
  Top Layer w10: R124.2@500,3516.38 R125.1@565,3516.38 586.38,3495 v1(597.5,3495) 608.62,3495 C123.2@630,3516.38 ; MSP101.1@1173.1,3598.11 1201.21,3570 v1(1205,3570)
  Bottom Layer w10: v1(597.5,3495) 637.5,3455 980,3455 1095,3570 v1(1205,3570)
EZFET_AVCC: C116.2 MSP102.6 R114.2 R115.1 | length 950.8
  Top Layer w8: v1(955,4145) C116.2@955,4186.38 ; v1@1559.41,3915 v1@1562.2,3912.2 ; MSP102.6@1562.2,3965.2 v1@1562.2,3912.2 ; v1(1565,3910) 1564.41,3910 v1@1562.2,3912.2
  Top Layer w10: R114.2@865,4233.62 865,4231.38 881.38,4215 882.86,4215 910,4187.86 R115.1@910,4186.38
  Top Layer w12: R115.1@910,4186.38 C116.2@955,4186.38
  Bottom Layer w8: v1(955,4145) 1025,4075 1295,4075 1375,3995 1518.58,3995 1565,3948.58 v1(1565,3910) v1@1560,3915
EZFET_AVCCOUT: C115.2 MSP102.1 R112.2 R113.1 | length 1045.4
  Top Layer w8: v1(1475,4145) 1470,4140 1470,4095 1486.61,4078.39 MSP102.1@1500.2,4078.39 ; R112.2@1695,3643.62 1694.13,3643.62 1694.13,3720.5 R113.1@1695,3721.38 ; C115.2@1695,3846.38 1665,3816.38 1665,3751.38 R113.1@1695,3721.38 ; v1(1730,3735) 1716.38,3721.38 R113.1@1695,3721.38
  Bottom Layer w8: v1(1475,4145) 1661.09,4145 1805,4001.09 1805,3810 v1(1730,3735)
EZFET_AVCCOUT2ADC: C122.2 MSP101.2 R121.2 R122.1 | length 298.4
  Top Layer w8: MSP101.2@1187.01,3612.03 1199.05,3600 1250,3600 1311.38,3538.62 C122.2@1345,3538.62 R121.2@1455,3538.62
EZFET_DCDCCAL0: MSP102.12 R126.1 | length 373.2
  Top Layer w8: MSP102.12@1649.8,4078.39 1696.61,4078.39 1745,4030 1745,3816.38 R126.1@1776.38,3785
EZFET_DCDCCAL1: MSP102.2 R127.1 | length 973
  Top Layer w8: v1(1495,4180) 1473.41,4180 1468.41,4175 1449.13,4155.72 1449.13,4092.39 1450.87,4090.65 1450.87,4089.13 1487.2,4052.8 MSP102.2@1500.2,4052.8 ; v1(1750.37,3700.37) 1750,3700 1750,3696.38 R127.1@1776.38,3670
  Bottom Layer w8: v1(1495,4180) 1645,4180 1650,4175 1655,4180 1823.62,4011.38 1823.62,3773.62 v1(1750.37,3700.37)
EZFET_DCDCCAL2: MSP102.11 R128.2 | length 395.1
  Top Layer w8: MSP102.11@1649.8,4052.8 1692.2,4052.8 1725,4020 1725,3786.38 R128.2@1776.38,3735
EZFET_DCDCIO0: MSP101.5 MSP102.4 | length 537.4
  Top Layer w8: MSP101.5@1228.77,3653.79 1210,3672.56 1210,3705 1290,3785 v1(1290,3860) ; v1@1500.2,3969.8 MSP102.4@1500.2,4001.61
  Bottom Layer w8: v1(1290,3860) 1290.87,3860.87 1334.28,3860.87 1438.41,3965 v1(1505,3965)
EZFET_DCDCIO1: MSP101.6 MSP102.5 | length 497.1
  Top Layer w8: MSP101.6@1242.69,3667.71 1230,3680.4 1230,3695 1320,3785 v1(1320,3835) ; v1(1535,3935) 1536.61,3936.61 MSP102.5@1536.61,3965.2
  Bottom Layer w8: v1(1320,3835) 1345,3835 1445,3935 v1(1535,3935)
EZFET_DCDCPULSE: MSP101.28 MSP102.3 R118.2 | length 836.1
  Top Layer w8: MSP101.28@1228.76,3996.22 1249.29,4016.75 1291.75,4016.75 1370,4095 1415,4095 1475,4035 1475,4027.2 ; MSP102.3@1500.2,4027.2 1475,4027.2 ; v1(1590,3875) 1558.41,3875 1479.13,3954.28 1479.13,3980.87 1475,3985 1475,4027.2 ; v1(1775,3975) 1775,4018.62 R118.2@1776.38,4020
  Bottom Layer w8: v1(1590,3875) 1590.87,3874.13 1674.13,3874.13 v1(1775,3975)
EZFET_DCDCRST: MSP101.7 MSP102.9 TP108.1 | length 835.3
  Top Layer w8: MSP101.7@1256.61,3681.63 1265.44,3672.8 1265.44,3656.96 1255,3646.52 1255,3620 1295,3580 v1(1535,3580) ; TP108.1@1600,3715 1620,3735 1620,3835 1649.8,3864.8 MSP102.9@1649.8,4001.61
  Bottom Layer w8: v1(1535,3580) 1535,3650 TP108.1@1600,3715
EZFET_DCDCTEST: MSP101.8 MSP102.10 TP109.1 | length 897.3
  Top Layer w8: MSP101.8@1270.53,3695.55 1285,3681.08 1285,3654.07 1275,3644.07 1275,3625 1300,3600 1505,3600 1520,3615 TP109.1@1600,3615 1658,3673 1658,3732 1645,3745 1645,3830 1665.68,3850.68 1665.68,3980 1675,3989.32 1675,4020 1667.8,4027.2 MSP102.10@1649.8,4027.2
EZFET_DM: IC102.4 J102.2 R103.1 | length 411.1
  Top Layer w10: IC102.4@411.81,3845.31 439.68,3845.31 v1(460,3825) R103.1@506.38,3825 ; v1(440,3955) 440,4000 474.41,4034.41 J102.2@474.41,4098.19
  Bottom Layer w10: v1(440,3955) 425,3940 425,3905 460,3870 v1(460,3825)
EZFET_DP: IC102.1 J102.3 R104.1 | length 633
  Top Layer w10: v1(360,3915) 380,3915 389.17,3905.83 IC102.1@389.17,3884.69 369.69,3884.69 355,3870 355,3795 470,3680 R104.1@506.38,3680 ; v1(500,4015) J102.3@500,4098.19
  Bottom Layer w10: v1(360,3915) 460,4015 v1(500,4015)
EZFET_HOSTSCL: MSP101.35 MSP102.7 R117.2 | length 793.6
  Top Layer w8: R117.2@1075,4166.38 v1(1075,4105) 1075,4058.11 MSP101.35@1109.07,4024.05 ; MSP102.7@1587.8,3965.2 1587.8,3937.2 1590,3935 1590,3930 v1(1595,3935)
  Bottom Layer w8: v1(1075,4105) 1095,4105 1105,4095 1300,4095 1384.13,4010.87 1525.16,4010.87 1595,3941.03 v1(1595,3935)
EZFET_HOSTSDA: MSP101.34 MSP102.8 R116.2 | length 841.7
  Top Layer w8: R116.2@1115,4166.38 v1(1115,4125) 1100.87,4110.87 1100.87,4060.08 MSP101.34@1122.99,4037.97 ; MSP102.8@1613.39,3965.2 1625,3953.58 1625,3905 v1(1620,3900)
  Bottom Layer w8: v1(1115,4125) 1130,4125 1140,4115 1305,4115 1390.87,4029.13 1535.87,4029.13 1604.13,3960.87 1605.72,3960.87 1620.87,3945.72 1620.87,3900.87 v1(1620,3900)
EZFET_LED0: MSP101.20 R101.2 | length 303.1
  Top Layer w8: R101.2@1241.38,4130 1241.38,4088.62 1280,4050 v1(1280,4045) ; MSP101.20@1340.14,3884.84 1356.61,3901.3 v1(1356.61,3974.13)
  Bottom Layer w8: v1(1280,4045) 1285.73,4045 v1(1356.61,3974.13)
EZFET_LED1: MSP101.21 R102.2 | length 362.2
  Top Layer w8: v1(1235,4045) 1205,4075 1205,4138.62 R102.2@1241.38,4175 ; v1(1325,3955) 1339.13,3940.87 1339.13,3911.67 MSP101.21@1326.22,3898.76
  Bottom Layer w8: v1(1235,4045) 1235,4050 1325,3960 v1(1325,3955)
EZFET_NC_TMSC: MSP101.45
EZFET_PU.0/DP: C111.1 MSP101.50 R104.2 R105.2 R106.2 | length 622
  Top Layer w8: C111.1@648.62,3680 648.62,3703.62 v1(715,3770) 690,3770 685,3775 R106.2@648.62,3775 ; v1(885,3780) 929,3780 MSP101.50@942.01,3793.01
  Top Layer w10: R104.2@553.62,3680 583.62,3650 640.5,3650 648.62,3658.12 C111.1@648.62,3680 ; R105.2@601.38,3825 R106.2@648.62,3777.76
  Bottom Layer w8: v1(715,3770) 740,3770 750,3780 v1(885,3780)
EZFET_PU.1/DM: C110.1 MSP101.52 R103.2 | length 695.4
  Top Layer w8: v1(465,3730) 465,3765 475,3775 C110.1@506.38,3775 ; v1@913.13,3750 945,3750 946.87,3751.87 956.57,3751.87 MSP101.52@969.86,3765.16
  Top Layer w10: C110.1@506.38,3775 553.62,3822.24 R103.2@553.62,3825
  Bottom Layer w8: v1(465,3730) 500,3695 690,3695 745,3750 v1(910,3750)
EZFET_PUR: MSP101.51 R105.1 | length 441.3
  Top Layer w8: R105.1@648.62,3825 648.62,3863.62 v1(650,3865) ; MSP101.51@955.93,3779.09 985,3808.15 v1(985,3810)
  Bottom Layer w8: v1(650,3865) 780,3865 795,3850 945,3850 v1(985,3810)
EZFET_RST: C112.2 MSP101.64 R109.2 TP107.1 | length 1298.8
  Top Layer w8: v1(540,3470) 570,3470 575,3465 700,3465 765,3400 1140,3400 1205,3465 1205,3538.62 ; MSP101.64@1136.93,3598.09 1175,3560.02 C112.2@1175,3538.62 1205,3538.62 ; R109.2@1235,3538.62 1205,3538.62
  Bottom Layer w8: TP107.1@200,3400 270,3470 v1(540,3470)
EZFET_SBWTCK: MSP101.44 R129.1 | length 796.6
  Top Layer w8: MSP101.44@983.79,3898.77 1007.56,3875 v1(1025,3875) ; R129.1@1273.62,3350 1313.62,3390 v1(1335,3390)
  Bottom Layer w8: v1(1025,3875) 1150,3750 1150,3720 1265,3605 1265,3525 1235,3495 1235,3440 1285,3390 v1(1335,3390)
EZFET_SBWTDIO: MSP101.43 R130.1 | length 678.7
  Top Layer w8: MSP101.43@997.71,3912.29 1006.13,3903.87 1053.87,3903.87 v1(1055,3905) ; R130.1@1273.62,3400 1280,3406.38 v1(1280,3435)
  Bottom Layer w8: v1(1055,3905) 1055,3875 1170,3760 1170,3725 1285,3610 1285,3520 1265,3500 1265,3450 v1(1280,3435)
EZFET_SHIELD: C126.2 IC102.5 J102.6 J102.7 J102.8 J102.9 J102.10 J102.11 R123.2 | length 1040.5
  Top Layer w12: J102.10@344.49,4202.91 344.49,4170.93 J102.11@403.05,4112.36 403.05,4128.05 463.09,4188.09 J102.9@463.09,4202.91 J102.8@536.91,4202.91 536.91,4188.09 596.95,4128.05 J102.6@596.95,4112.36 J102.7@655.51,4170.93 ; IC102.5@411.81,3865 535,3865 553.62,3883.62 R123.2@553.62,3915 553.62,3970 v1(600,3970)
  Bottom Layer w12: v1(600,3970) 655.51,4025.51 J102.7@655.51,4202.91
